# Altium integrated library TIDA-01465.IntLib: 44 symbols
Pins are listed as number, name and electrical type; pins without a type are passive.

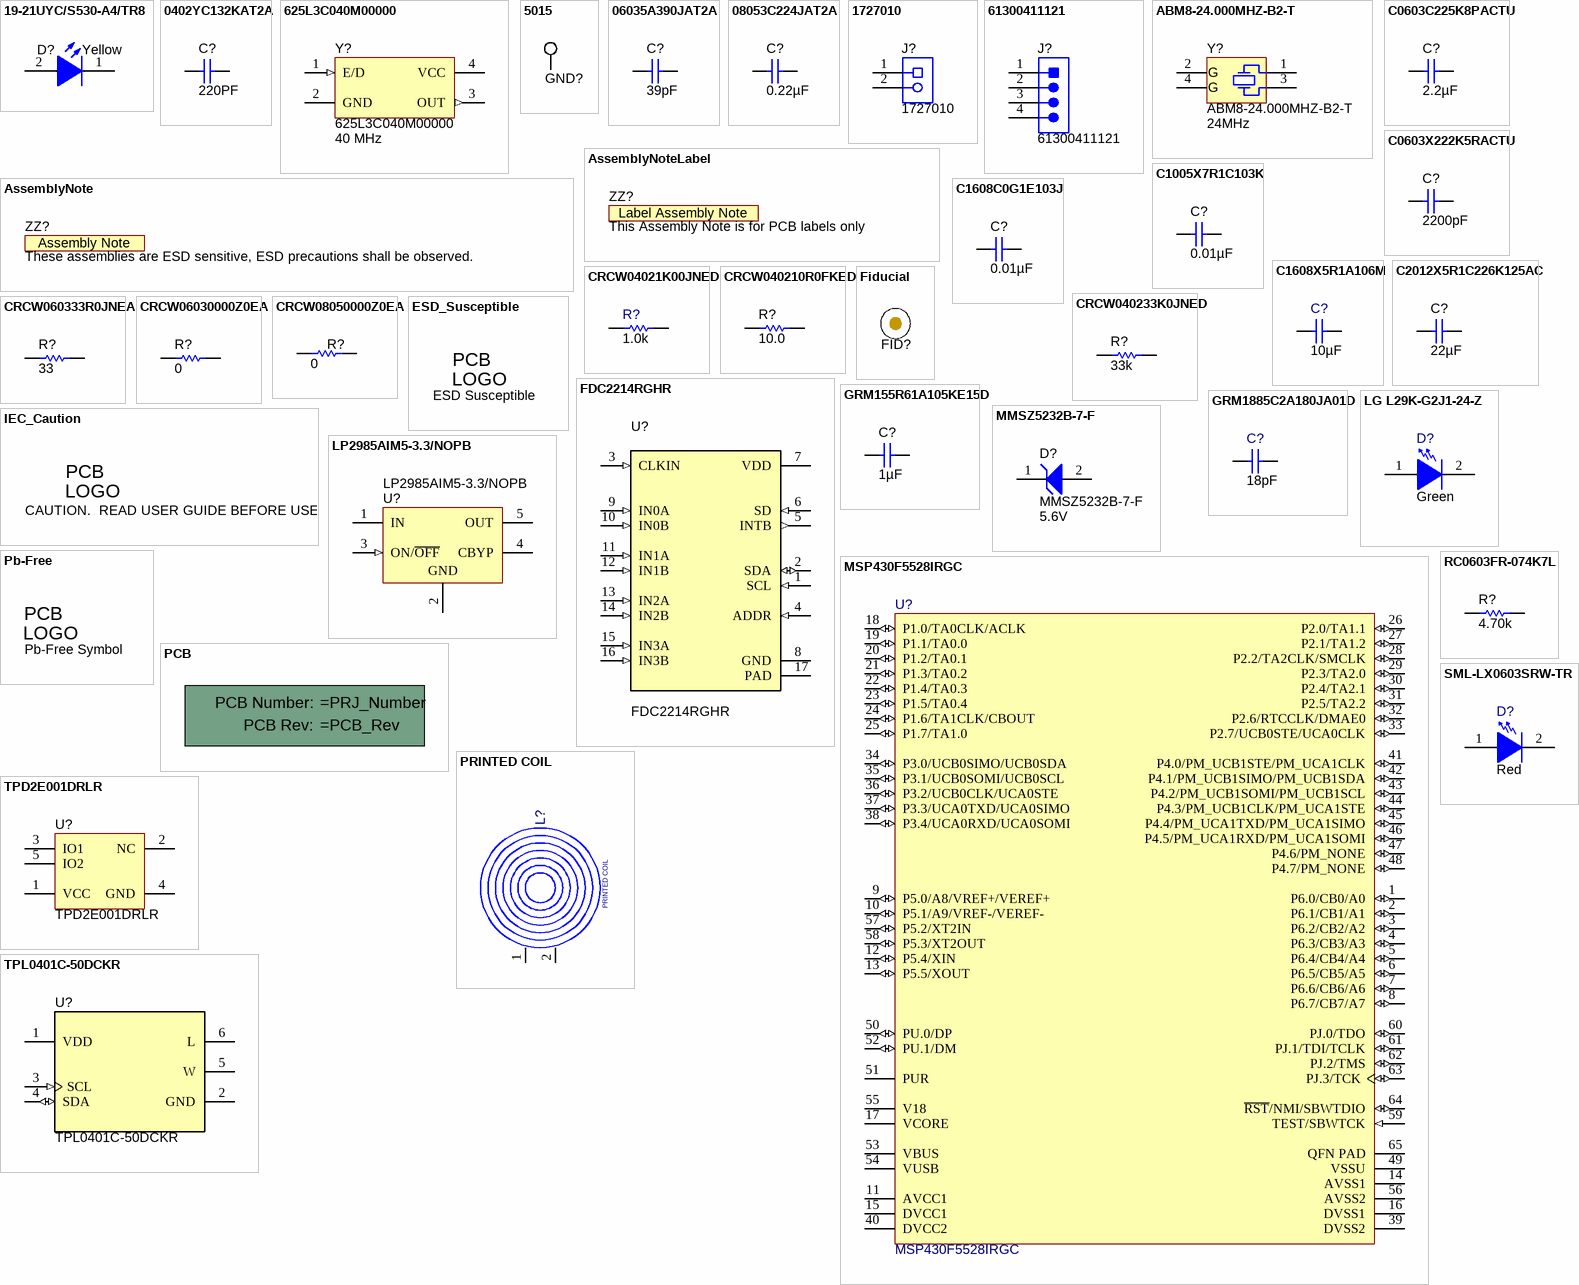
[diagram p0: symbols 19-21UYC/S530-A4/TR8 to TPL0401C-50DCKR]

## 19-21UYC/S530-A4/TR8
designator D?  value Yellow  (hidden comment: 19-21UYC/S530-A4/TR8)
LED, Yellow, SMD; Manufacturer: Everlight; Type: AlInGaP; Vf_V: 2; Value2: 2V; Io_A: 0.02; Vr_V: 5; Ir_A: 1e-005; Tjmax_C: 85; Value1: W; Angle: 100; U/M: EA
signal-integrity model Diode
footprint 19-21_Yellow
pins: 1 K, 2 A

## 0402YC132KAT2A
designator C?, comment value 220PF  (hidden comment: C1005C0G1H221F050BA)
CAP CER 220PF 50V 1% NP0 0402; Manufacturer: TDK Corporation; Polarized: N; CompType: Capacitor; U/M: EA; Cap_F: 0.0000000013; Tolerance_%: 10; VDC_V: 16; TempCo: X7R; TaMin_C: -55; TaMax_C: 125; Cap_Case: 0402
signal-integrity model Cap
simulation model Cap
footprint 0402
footprint 0402M
footprint 0402L
pins: 1, 2

## 625L3C040M00000
designator Y?  Frequency: 40 MHz
OSC, 40 MHz, 3.3 V, SMD; Manufacturer: CTS Electrocomponents; SymbolCreator: a0411947; CompType: Oscillator; U/M: EA; TaMin_C: -20; TaMax_C: 70; Frequency Stability: ±50ppm
footprint OSC_CTS_625
pins: 1 E/D (in), 2 GND (power), 3 OUT (out), 4 VCC (power)

## 5015
designator GND?  (value not drawn)
Test Point, Miniature, SMT; Manufacturer: Keystone; CompType: Test Point Loop; U/M: EA
footprint Testpoint_Keystone_Miniature
pins: 1

## 06035A390JAT2A
designator C?  ValueDisplayed: 39pF  (hidden comment: 06035A390JAT2A)
CAP, CERM, 39 pF, 50 V, +/- 5%, C0G/NP0, 0603; Manufacturer: AVX; Polarized: N; CompType: Capacitor; Value: 39pF; U/M: EA; Cap_F: 0.000000000039; Tolerance_%: 5; ESR_ohm: 0.191; Value1: 0.191 ohm; VDC_V: 50; Value2: 50V; TaMin_C: -55; TaMax_C: 125; Cap_Case: 0603; SizeArea_mm2: 1.28; SizeAreaWB_mm2: 4.68; SizeX_mm: 1.6; SizeY_mm: 0.8; SizeZ_mm: 1; AEC Category: Q200
signal-integrity model Cap
simulation model Cap
footprint 0603
footprint 0603M
footprint 0603L
footprint 0603_HV
footprint 0603S
pins: 1, 2

## 08053C224JAT2A
designator C?  ValueDisplayed: 0.22µF  (hidden comment: 08053C224JAT2A)
CAP, CERM, 0.22 µF, 25 V, +/- 5%, X7R, 0805; Manufacturer: AVX; Polarized: N; CompType: Capacitor; Value: 0.22uF; U/M: EA; Cap_F: 0.00000022; Tolerance_%: 5; ESR_ohm: 0.016; Value1: 0.016 ohm; VDC_V: 25; Value2: 25V; TaMin_C: -55; TaMax_C: 125; Cap_Case: 0805
signal-integrity model Cap
simulation model Cap
footprint 0805_HV
footprint 0805
footprint 0805M
footprint 0805L
pins: 1, 2

## 1727010
designator J?
Conn Term Block, 2POS, 3.81mm, TH; Manufacturer: Phoenix Contact; SymbolCreator: a0412235; CompType: Terminal Block; U/M: EA; Value: 2x1
footprint PhoenixConact_1727010
pins: 1, 2

## 61300411121
designator J?
Header, 2.54 mm, 4x1, Gold, TH; Manufacturer: Wurth Elektronik; SymbolCreator: a0412235
footprint WURTH_61300411121
pins: 1, 2, 3, 4

## ABM8-24.000MHZ-B2-T
designator Y?  Frequency: 24MHz
Crystal, 24.000MHz, 18pF, SMD; Manufacturer: Abracon Corportation; SymbolCreator: a0412235; U/M: EA; TaMin_C: -20; TaMax_C: 70; Frequency Stability: ±50ppm
footprint XTAL_ABM8
pins: 1, 2 GND (power), 3, 4 GND (power)

## AssemblyNote
designator ZZ?, comment These assemblies are ESD sensitive, ESD precautions shall be observed.  (no BOM)
SymbolCreator: codlsc; CompType: AssemblyNote
footprint AssemblyNote

## AssemblyNoteLabel
designator ZZ?, comment This Assembly Note is for PCB labels only  (no BOM)
SymbolCreator: a0412235
footprint AssemblyNoteLabel

## C0603C225K8PACTU
designator C?  ValueDisplayed: 2.2µF  (hidden comment: C0603C225K8PACTU)
CAP, CERM, 2.2uF, 10V, +/-10%, X5R, 0603; Manufacturer: Kemet; Polarized: N; CompType: Capacitor; U/M: EA; Cap_F: 0.0000022; Tolerance_%: 10; Value1: Unknown; TaMin_C: -55; TaMax_C: 85; Cap_Case: 0603
signal-integrity model Cap
simulation model Cap
footprint 0603
footprint 0603M
footprint 0603L
footprint 0603_HV
pins: 1, 2

## C0603X222K5RACTU
designator C?  ValueDisplayed: 2200pF  (hidden comment: C0603X222K5RACTU)
CAP, CERM, 2200pF, 50V, +/-10%, X7R, 0603; Manufacturer: Kemet; Polarized: N; CompType: Capacitor; U/M: EA; Cap_F: 0.0000000022; Tolerance_%: 10; VDC_V: 50; TaMin_C: -55; TaMax_C: 125; Cap_Case: 0603
signal-integrity model Cap
simulation model Cap
footprint 0603
footprint 0603M
footprint 0603L
footprint 0603_HV
footprint C603
pins: 1, 2

## C1005X7R1C103K
designator C?  ValueDisplayed: 0.01µF  (hidden comment: C1005X7R1C103K)
CAP, CERM, 0.01 µF, 16 V, +/- 10%, X7R, 0402; Manufacturer: TDK; Polarized: N; CompType: Capacitor; Value: 0.01uF; U/M: EA; Cap_F: 0.00000001; Tolerance_%: 10; ESR_ohm: 0.0623; Value1: 0.0623 ohm; VDC_V: 16; Value2: 16V; TaMin_C: -55; TaMax_C: 125; Cap_Case: 0402
signal-integrity model Cap
simulation model Cap
footprint 0402
footprint 0402M
footprint 0402L
footprint 0402S
pins: 1, 2

## C1608C0G1E103J
designator C?  ValueDisplayed: 0.01µF  (hidden comment: C1608C0G1E103J)
CAP, CERM, 0.01uF, 25V, +/-5%, C0G/NP0, 0603; Manufacturer: TDK; Polarized: N; CompType: Capacitor; U/M: EA; Cap_F: 0.00000001; Tolerance_%: 5; VDC_V: 25; TaMin_C: -55; TaMax_C: 125; Cap_Case: 0603
signal-integrity model Cap
simulation model Cap
footprint 0603
footprint 0603M
footprint 0603L
footprint 0603_HV
pins: 1, 2

## C1608X5R1A106M
designator C?  ValueDisplayed: 10µF  (hidden comment: C1608X5R1A106M)
CAP, CERM, 10uF, 10V, +/-20%, X5R, 0603; Manufacturer: TDK; Polarized: N; CompType: Capacitor; U/M: EA; Cap_F: 0.00001; Tolerance_%: 20; ESR_Ohm: 0.0078; Value1: 0.0078 ohm; VDC_V: 10; IRMS_A: 1.85; TaMin_C: -55; TaMax_C: 85; Cap_Case: 0603
signal-integrity model Cap
simulation model Cap
footprint 0603
footprint 0603M
footprint 0603L
footprint 0603_HV
footprint 0603S
pins: 1, 2

## C2012X5R1C226K125AC
designator C?  ValueDisplayed: 22µF  (hidden comment: C2012X5R1C226K125AC)
CAP, CERM, 22uF, 16V, +/-10%, X5R, 0805; Manufacturer: TDK; Polarized: N; CompType: Capacitor; U/M: EA; Cap_F: 0.000022; Tolerance_%: 10; Value1: Unknown; VDC_V: 16; TaMin_C: -55; TaMax_C: 85; Cap_Case: 0805
signal-integrity model Cap
simulation model Cap
footprint 0805_HV
footprint 0805
footprint 0805M
footprint 0805L
pins: 1, 2

## CRCW04021K00JNED
designator R?  value 1.0k  (hidden comment: CRCW04021K00JNED)
RES, 1.0k ohm, 5%, 0.063W, 0402; Manufacturer: Vishay-Dale; CompType: Resistor; Res_ohm: 1000; Value_Code: 1k00; Tolerance_%: 5; Power_W: 0.063; VDC_V: 50; TempCo: 200 ppm/C; EIA_Code: E24; U/M: EA
signal-integrity model Resistor
simulation model Resistor
footprint 0402
footprint 0402M
footprint 0402L
footprint 0402S
pins: 1, 2

## CRCW040210R0FKED
designator R?  ValueDisplayed: 10.0  (hidden comment: CRCW040210R0FKED)
RES, 10.0, 1%, 0.063 W, 0402; Manufacturer: Vishay-Dale; CompType: Resistor; Value: 10.0; Res_ohm: 10; Value_Code: 10R0; Tolerance_%: 1; Power_W: 0.063; Value2: 0.063W; VDC_V: 50; TempCo: 100 ppm/C; EIA_Code: E96; U/M: EA
signal-integrity model Resistor
simulation model Resistor
footprint 0402
footprint 0402M
footprint 0402L
footprint 0402S
pins: 1, 2

## CRCW040233K0JNED
designator R?  value 33k  (hidden comment: CRCW040233K0JNED)
RES, 33k ohm, 5%, 0.063W, 0402; Manufacturer: Vishay-Dale; CompType: Resistor; Res_ohm: 33000; Value_Code: 33k0; Tolerance_%: 5; Power_W: 0.063; VDC_V: 50; TempCo: 200 ppm/C; EIA_Code: E24; U/M: EA
signal-integrity model Resistor
simulation model Resistor
footprint 0402
footprint 0402M
footprint 0402L
footprint 0402
pins: 1, 2

## CRCW060333R0JNEA
designator R?  value 33  (hidden comment: CRCW060333R0JNEA)
RES, 33 ohm, 5%, 0.1W, 0603; Manufacturer: Vishay-Dale; CompType: Resistor; Value_Code: 33R0; Tolerance_%: 5; Power_W: 0.1; VDC_V: 75; TempCo: 200 ppm/C; EIA_Code: E24; U/M: EA
signal-integrity model Resistor
simulation model Resistor
footprint 0603
footprint 0603M
footprint 0603L
footprint 0603_HV
pins: 1, 2

## CRCW06030000Z0EA
designator R?  value 0  (hidden comment: CRCW06030000Z0EA)
RES, 0 ohm, 5%, 0.1W, 0603; Manufacturer: Vishay-Dale; CompType: Resistor; Value_Code: 0000; Tolerance_%: 5; Power_W: 0.1; VDC_V: 75; TempCo: 200 ppm/C; EIA_Code: E24; U/M: EA
signal-integrity model Resistor
simulation model Resistor
footprint 0603
footprint 0603M
footprint 0603L
footprint 0603_HV
pins: 1, 2

## CRCW08050000Z0EA
designator R?  value 0  (hidden comment: CRCW08050000Z0EA)
RES, 0 ohm, 5%, 0.125W, 0805; Manufacturer: Vishay-Dale; CompType: Resistor; Value_Code: 0000; Tolerance_%: 5; Power_W: 0.125; VDC_V: 150; TempCo: 200 ppm/C; EIA_Code: E24; U/M: EA
signal-integrity model Resistor
simulation model Resistor
footprint 0805_HV
footprint 0805
footprint 0805M
footprint 0805L
pins: 1, 2

## ESD_Susceptible
designator Logo?, comment ESD Susceptible  (no BOM)
ESD Susceptible Symbol; SymbolCreator: a0412235
footprint ESD_Overlay_Large
footprint ESD_Overlay_Medium
footprint ESD_Overlay_Small

## FDC2214RGHR
designator U?
Noise-immune Capacitive Sensing Solution for Proximity Sensing, RGH0016A (WQFN-16); Manufacturer: Texas Instruments; SymbolCreator: a0411947; SizeArea_mm2: 16; SizeAreaWB_mm2: 25; SizeX_mm: 4; SizeZ_mm: 0.8; CompType: IC; U/M: EA
footprint RGH0016A
pins: 1 SCL (in), 2 SDA (io), 3 CLKIN (in), 4 ADDR (in), 5 INTB (out), 6 SD (in), 7 VDD (power), 8 GND (power), 9 IN0A (in), 10 IN0B (in), 11 IN1A (in), 12 IN1B (in), 13 IN2A (in), 14 IN2B (in), 15 IN3A (in), 16 IN3B (in), 17 PAD (power)
1 alternate drawing of the same symbol

## Fiducial
designator FID?  (value not drawn)
Fiducial mark.  There is nothing to buy or mount.; SymbolCreator: codlsc
footprint Fiducial10-30
footprint Fiducial10-20
footprint Fiducial15-30
footprint Fiducial20-40
footprint Fiducial6.4-20
footprint Fiducial10-30_TopLayerKeepOutOnly
footprint Fiducial6.4-20_TopLayerKeepOutOnly
footprint Fiducial10-20_TopLayerKeepOutOnly
footprint Fiducial15-30_TopLayerKeepOutOnly
footprint Fiducial20-40_TopLayerKeepOutOnly

## GRM155R61A105KE15D
designator C?  ValueDisplayed: 1µF  (hidden comment: GRM155R61A105KE15D)
CAP, CERM, 1uF, 10V, +/-10%, X5R, 0402; Manufacturer: MuRata; Polarized: N; CompType: Capacitor; U/M: EA; Cap_F: 0.000001; Tolerance_%: 10; Value1: Unknown; TaMin_C: -55; TaMax_C: 85; Cap_Case: 0402
signal-integrity model Cap
simulation model Cap
footprint 0402
footprint 0402M
footprint 0402L
pins: 1, 2

## GRM1885C2A180JA01D
designator C?  ValueDisplayed: 18pF  (hidden comment: GRM1885C2A180JA01D)
CAP, CERM, 18pF, 100V, +/-5%, C0G/NP0, 0603; Manufacturer: MuRata; Polarized: N; CompType: Capacitor; U/M: EA; Cap_F: 0.000000000018; Tolerance_%: 5; Value1: Unknown; VDC_V: 100; TaMin_C: -55; TaMax_C: 125; Cap_Case: 0603
signal-integrity model Cap
simulation model Cap
footprint 0603
footprint 0603M
footprint 0603L
footprint 0603_HV
footprint 0603S
pins: 1, 2

## IEC_Caution
designator Logo?, comment CAUTION.  READ USER GUIDE BEFORE USE  (no BOM)
IEC 61010-1 Caution Warning; SymbolCreator: a0412235
footprint IEC_Caution_Large
footprint IEC_Caution_Medium
footprint IEC_Caution_Small

## LG L29K-G2J1-24-Z
designator D?  value Green  (hidden comment: LG L29K-G2J1-24-Z)
LED, Green, SMD; Manufacturer: OSRAM; Vf_V: 1.7; Value2: 1.7V; Io_A: 0.002; Tjmax_C: 110; Value1: W; U/M: EA
signal-integrity model Diode
footprint LG L29K_GREEN
pins: 1 A, 2 K

## LP2985AIM5-3.3/NOPB
designator U?
Micropower 150 mA Low-Noise Ultra Low-Dropout Regulator, 5-pin SOT-23, Pb-Free; Manufacturer: Texas Instruments; PackageTopMarking: L0RA*XTT; PowerWise: N; CompType: LDO IC
footprint MF05A_N (SOT23, 5-Leads, Body 2.9x1.6mm, Pitch 0.95mm, Lead Span 2.8mm, IPC Medium Density)
footprint MF05A_L (SOT23, 5-Leads, Body 2.9x1.6mm, Pitch 0.95mm, Lead Span 2.8mm, IPC High Density)
footprint MF05A_M (SOT23, 5-Leads, Body 2.9x1.6mm, Pitch 0.95mm, Lead Span 2.8mm, IPC Low Density)
pins: 1 IN (power), 2 GND (power), 3 ON/~{OFF} (in), 4 CBYP, 5 OUT (power)

## MMSZ5232B-7-F
designator D?  value 5.6V
Diode, Zener, 5.6V, 500mW, SOD-123; Manufacturer: Diodes Inc.; U/M: EA; Power_W: 0.5; Vz_V: 5.6; Value1: 0.5W; RJA_CperW: 350
signal-integrity model Diode
footprint SOD-123
pins: 1 K, 2 A

## MSP430F5528IRGC
designator U?
Mixed Signal MicroController, RGC0064B; Manufacturer: Texas Instruments; Alternate Manufacturer: None; ADC: 12-bit SAR; ADC Channels: 16; Brown Out Reset: Yes; DMA: 3; Eco-Plan: Green (RoHS & no Sb/Br); Flash(KB): 128; Frequency(MHz): 25; GPIO: 47; Multiplier: 32x32; SRAM(B): 8192; SubFamily: 5 Series; Timers - 16-bit: 4; USB: 1; USCI_A (UART/LIN/IrDA/SPI): 2; SymbolCreator: Altium/a0412235; CompType: IC; U/M: EA
footprint RGC0064B
footprint RGC0064B_NV
pins: 1 P6.0/CB0/A0 (io), 2 P6.1/CB1/A1 (io), 3 P6.2/CB2/A2 (io), 4 P6.3/CB3/A3 (io), 5 P6.4/CB4/A4 (io), 6 P6.5/CB5/A5 (io), 7 P6.6/CB6/A6 (io), 8 P6.7/CB7/A7 (io), 9 P5.0/A8/VREF+/VEREF+ (io), 10 P5.1/A9/VREF-/VEREF- (io), 11 AVCC1 (power) "Analog power supply", 12 P5.4/XIN (io), 13 P5.5/XOUT (io), 14 AVSS1 (power) "Analog ground supply", 15 DVCC1 (power) "Digital power supply", 16 DVSS1 (power) "Digital ground supply", 17 VCORE "Regulated core power supply output (internal use only, no external current loading)", 18 P1.0/TA0CLK/ACLK (io), 19 P1.1/TA0.0 (io), 20 P1.2/TA0.1 (io), 21 P1.3/TA0.2 (io), 22 P1.4/TA0.3 (io), 23 P1.5/TA0.4 (io), 24 P1.6/TA1CLK/CBOUT (io), 25 P1.7/TA1.0 (io), 26 P2.0/TA1.1 (io), 27 P2.1/TA1.2 (io), 28 P2.2/TA2CLK/SMCLK (io), 29 P2.3/TA2.0 (io), 30 P2.4/TA2.1 (io), 31 P2.5/TA2.2 (io), 32 P2.6/RTCCLK/DMAE0 (io), 33 P2.7/UCB0STE/UCA0CLK (io), 34 P3.0/UCB0SIMO/UCB0SDA (io), 35 P3.1/UCB0SOMI/UCB0SCL (io), 36 P3.2/UCB0CLK/UCA0STE (io), 37 P3.3/UCA0TXD/UCA0SIMO (io), 38 P3.4/UCA0RXD/UCA0SOMI (io), 39 DVSS2 (power) "Digital ground supply", 40 DVCC2 (power) "Digital power supply", 41 P4.0/PM_UCB1STE/PM_UCA1CLK (io), 42 P4.1/PM_UCB1SIMO/PM_UCB1SDA (io), 43 P4.2/PM_UCB1SOMI/PM_UCB1SCL (io), 44 P4.3/PM_UCB1CLK/PM_UCA1STE (io), 45 P4.4/PM_UCA1TXD/PM_UCA1SIMO (io), 46 P4.5/PM_UCA1RXD/PM_UCA1SOMI (io), 47 P4.6/PM_NONE (io), 48 P4.7/PM_NONE (io), 49 VSSU (power) "USB PHY ground supply", 50 PU.0/DP (io), 51 PUR "USB pullup resistor pin (open drain). The voltage level at the PUR pin is used to invoke the default USB BSL. Recommended 1-Mohm resistor to ground. See USB BSL for more information.", 52 PU.1/DM (io), 53 VBUS (power) "USB LDO input (connect to USB power source)", 54 VUSB (power) "USB LDO output", 55 V18 "USB regulated power (internal use only, no external current loading)", 56 AVSS2 (power) "Analog ground supply", 57 P5.2/XT2IN (io), 58 P5.3/XT2OUT (io), 59 TEST/SBWTCK (in), 60 PJ.0/TDO (io), 61 PJ.1/TDI/TCLK (io), 62 PJ.2/TMS (io), 63 PJ.3/TCK (io), 64 ~{RST}/NMI/SBWTDIO (io), 65 QFN PAD (power) "QFN package pad connection to VSS recommended."

## Pb-Free
designator Logo?, comment Pb-Free Symbol  (no BOM)
SymbolCreator: a0412235
footprint Pb-Free_Overlay_Medium
footprint Pb-Free_Overlay_Small

## PCB
designator !PCB?, comment Printed Circuit Board  (value not drawn)  (mechanical)
Manufacturer: Any; PartNumber: TIDA-01467; SymbolCreator: a0412235; CompType: PCB
1 alternate drawing of the same symbol

## PRINTED COIL
designator L?
8.2MM 2-layer Coil 3.5uH
footprint Printed_Coil_8.2MM
footprint PCBComponent_1
pins: 1 ., 2 .

## RC0603FR-074K7L
designator R?  value 4.70k  (hidden comment: RC0603FR-074K7L)
RES, 4.70k ohm, 1%, 0.1W, 0603; Manufacturer: Yageo America; CompType: Resistor; Res_ohm: 4700; Value_Code: 4k70; Tolerance_%: 1; Power_W: 0.1; VDC_V: 150; TempCo: 200 ppm/C; U/M: EA
signal-integrity model Resistor
simulation model Resistor
footprint 0603
footprint 0603M
footprint 0603L
footprint 0603_HV
footprint 0603S
pins: 1, 2

## SML-LX0603SRW-TR
designator D?  value Red  (hidden comment: SML-LX0603SRW-TR)
LED, Super Red, SMD; Manufacturer: Lumex; Vf_V: 1.7; Value2: 1.7V; Io_A: 0.02; Value1: W; U/M: EA
signal-integrity model Diode
footprint SML-LX0603SRW_SuperRed
pins: 1 A, 2 K

## TPD2E001DRLR
designator U?
Low-Capacitance + / - 15 kV ESD-Protection Array for High-Speed Data Interfaces, 2 Channels, -40 to +85 degC, 5-pin SOT (DRL), Green (RoHS & no Sb/Br); Manufacturer: Texas Instruments; Alternate Manufacturer: None; Alternate PartNumber: Equivalent; Breakdown Voltage(Min)(V): 11; IEC 61000-4-2 Air-Gap(+/- kV): 15; IEC 61000-4-2 Contact(+/- kV): 8; IO Capacitance(Typ)(pF): 1.5; IO Leakage Current(nA): 1; SubFamily: ESD Solution; USB High Speed: TRUE
footprint DRL0005A (SOTFL, 5-Flat Leads, Body 1.2x1.6x0.6mm, Pitch 0.5mm, TI Recommended)
footprint DRL0005A_N (SOTFL, 5-Flat Leads, Body 1.2x1.6x0.6mm, Pitch 0.5mm, IPC Medium Density)
footprint DRL0005A_L (SOTFL, 5-Flat Leads, Body 1.2x1.6x0.6mm, Pitch 0.5mm, IPC High Density)
footprint DRL0005A_M (SOTFL, 5-Flat Leads, Body 1.2x1.6x0.6mm, Pitch 0.5mm, IPC Low Density)
pins: 1 VCC (power) "Power-supply input. Bypass VCC to GND with a 0.1-uF ceramic capacitor.", 2 NC "No connection. Not internally connected.", 3 IO1 "ESD-protected channel", 4 GND (power) "Ground", 5 IO2 "ESD-protected channel"

## TPL0401C-50DCKR
designator U?
128 TAPS Single Channel Digital Potentiometer with I2C Interface, DCK0006A (SOT-6); Manufacturer: Texas Instruments; SymbolCreator: a0411947; SizeArea_mm2: 4.2; SizeAreaWB_mm2: 9.3; SizeX_mm: 2.1; SizeY_mm: 2; SizeZ_mm: 1.1; CompType: IC; U/M: EA
footprint DCK0006A_N
footprint DCK0006A_M
footprint DCK0006A_L
pins: 1 VDD (power) "Positive Supply Voltage", 2 GND (power) "Ground", 3 SCL (in) "I2C Clock", 4 SDA (io) "I2C Data", 5 W "Wiper terminal", 6 L "High terminal"

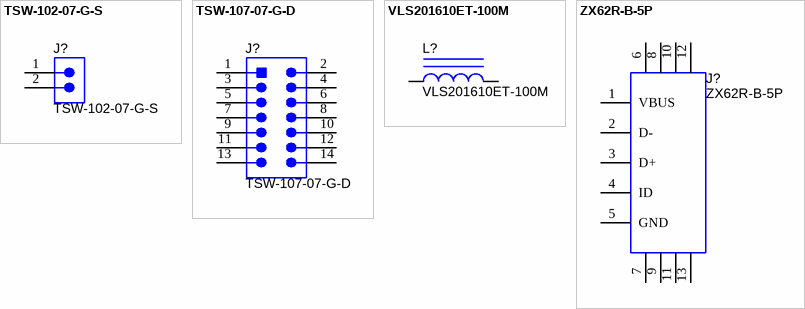
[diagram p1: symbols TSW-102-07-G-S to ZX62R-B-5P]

## TSW-102-07-G-S
designator J?
Header, TH, 100mil, 2x1, Gold plated, 230 mil above insulator; Manufacturer: Samtec, Inc.; SymbolCreator: a0412235; U/M: EA
footprint TSW-102-07-G-S
footprint TSW-102-07-X-S
pins: 1, 2
1 alternate drawing of the same symbol

## TSW-107-07-G-D
designator J?
Header, 100mil, 7x2, Gold, TH; Manufacturer: Samtec; SymbolCreator: a0412235; U/M: EA
footprint TSW-107-07-G-D
footprint TSW-107-07-X-D
pins: 1, 2, 3, 4, 5, 6, 7, 8, 9, 10, 11, 12, 13, 14

## VLS201610ET-100M
designator L?
Inductor, Shielded, Ferrite, 10 µH, 0.4 A, 1.38 ohm, SMD; Manufacturer: TDK; Value: 10uH; Ind_H: 10.0E-6; ValueDisplayed: 10µH; Imax_A: 0.4; Irms: 0.42A @ 40C rise; Isat: 0.4A @ 30% inductance drop; DCR_ohm: 1.38; Value2: 0.4A
signal-integrity model Inductor
simulation model Inductor
footprint VLS201610ET
pins: 1, 2

## ZX62R-B-5P
designator J?
Connector, Receptacle, Micro-USB Type B, SMT; Manufacturer: Hirose Electric Co. Ltd.; SymbolCreator: a0799628; U/M: EA
footprint Hirose_ZX62R-B-5P
pins: 1 VBUS, 2 D-, 3 D+, 4 ID, 5 GND, 6, 7, 8, 9, 10, 11, 12, 13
